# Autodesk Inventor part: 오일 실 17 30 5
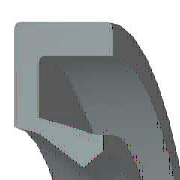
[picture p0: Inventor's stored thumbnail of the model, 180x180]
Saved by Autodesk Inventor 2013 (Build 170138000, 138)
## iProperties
Created: 2012-02
Part Number: 오일 실 17 30 5
Material: 고무
Description: 오일 실 - 스프링 장착, 비스프링, 고무 덮개 G
Document SubType Name: Modeling
Standard: JIS B 2402
Designer: mduedu
Standards Organization: JIS
Language: ko-KR
Size Designation: 17 30 5 A
Categories: <MemberInstance><Categories><Category DisplayName="샤프트 부품" InternalName="7f7aeb1f-a693-4053-b835-cee3144e0d98" Mnemonic="SHFT"><Category DisplayName="실링" Intern
Density: 0.93 g/cm^3
Mass: 1.22959 g
Surface Area: 18.6191 cm^2
Volume: 1.32214 cm^3
IsCustomPart: 1
Author: mduedu
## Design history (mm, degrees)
fillet "모깎기2" dims "d41" = 0.5
fillet "모깎기3" dims "d42" = 0.5
body "Solid1"
revolve "회전1" stored, may be unused: angle "d29" = 360 deg
fillet "모깎기1" dims "d34" = 0.25 (= 0.05 x b)
sketch "스케치2"
  geometry: L1 (9.58, -3.438)-(9.905, -5); L2 (9.147, -3.282)-(9.58, -3.438); L3 (8.5, -1.72)-(9.147, -3.282); L4 (9.682, -1.22)-(8.5, -1.72); L5 (10.811, -3.75)-(9.682, -1.22); L6 (12.111, -3.75)-(10.811, -3.75); L7 (13.556, -1.25)-(12.111, -3.75); L8 (13.556, 0)-(13.556, -1.25); L9 (15, 0)-(13.556, 0); L10 (15, -5)-(15, 0); L11 (9.905, -5)-(15, -5); L12 (0, -9.6)-(0, 1.6) reference; L13 (28, 0)-(14, 0) reference
  constraints: 22 end point, 3 horizontal, 2 vertical
  dimensions: "d2" = 5 distance of L10.start L9.start (= b); "d4" = 1.25 vertical distance of L5.start L1.end (= 0.25 x b); "d6" = 1.44444 distance of L9.start L8.start (= 0.111111 x dd - 0.111111 x Diam); "d8" = 1.25 distance of L8.start L7.start (= 0.25 x b); "d10" = 1.44444 horizontal distance of L7.start L6.start (= 0.111111 x dd - 0.111111 x Diam); "d12" = 1.21951 vertical distance of L9.start L4.start (= 0.243902 x b); "d14" = 1.18182 horizontal distance of L4.start L3.start (= 0.0909091 x dd - 0.0909091 x Diam); "d16" = 0.5 vertical distance of L4.start L3.start (= 0.1 x b); "d18" = 1.3 distance of L6.start L5.start (= 0.1 x dd - 0.1 x Diam); "d20" = 1.5625 vertical distance of L3.start L2.start (= 0.3125 x b); "d22" = 0.64677 horizontal distance of L3.start L2.start (= 0.0497512 x dd - 0.0497512 x Diam); "d24" = 0.325 horizontal distance of L1.start L1.end (= 0.025 x dd - 0.025 x Diam); "d26" = 1.5625 vertical distance of L1.start L1.end (= 0.3125 x b); "d28" = 0.43333 horizontal distance of L2.start L1.start (= 0.0333333 x dd - 0.0333333 x Diam); "d35" = 0 distance between parallel lines of L13 L9; "d36" = 15 distance between parallel lines of L12 L10 (= 0.5 x dd); "d37" = 8.5 distance from line of L12 L3.start (= 0.5 x Diam)
other parameters: "Diam" = 17 [user parameter; used in 8 equation terms], "b" = 5 [user parameter; used in 8 equation terms], "d1" = 8 (derived), "d3" = 2 (derived), "d5" = 2.22222 (derived), "d7" = 2 (derived), "d9" = 2.22222 (derived), "d11" = 1.95122 (derived), "d13" = 1.81818 (derived), "d15" = 0.8 (derived), "d17" = 2 (derived), "d19" = 2.5 (derived), "d21" = 0.99502 (derived), "d23" = 0.5 (derived), "d25" = 2.5 (derived), "d27" = 0.66667 (derived), "d38" = 0
